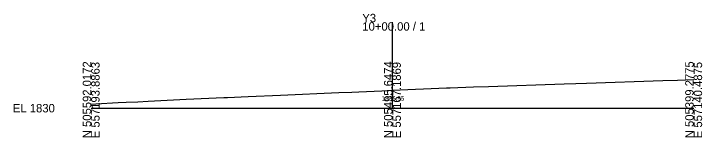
# Model space of a CAD drawing. Extents: x -26 to 1503, y -10 to 2064.
# Drawn here: x -25.7 to 202.8, y -9.7 to 31.5 of the extents above; entities that cross this region are included whole.
import ezdxf

# ---------------------------------------------------------------- set-up
doc = ezdxf.new("R2010")
doc.units = 0
for name, color, linetype in [('Default', 7, 'Continuous'), ('Exist Cross Section Cell', 7, 'Continuous'), ('Exist XS Center Line Elevation Label', 7, 'Continuous'), ('Exist XS Ground Line', 7, 'Continuous')]:
    doc.layers.add(name, color=color, linetype=linetype)

msp = doc.modelspace()

# ---------------------------------------------------------------- linework, layer by layer
at = {"layer": 'Exist Cross Section Cell'}
for p, q in [((100, 0), (100, 28.63)), ((0, 0), (100, 0)), ((100, 0), (200, 0))]:
    msp.add_line(p, q, dxfattribs=at)
at = {"layer": 'Exist XS Ground Line'}
for p, q in [((164.46, 8.31), (189.72, 9.17)), ((189.72, 9.17), (194.62, 9.34)), ((194.62, 9.34), (200, 9.54)), ((119.18, 6.78), (126.95, 7.06)), ((126.95, 7.06), (131.92, 7.21)), ((131.92, 7.21), (156.99, 8.06)), ((156.99, 8.06), (160.86, 8.19)), ((160.86, 8.19), (164.46, 8.31)), ((62.9, 4.35), (82.18, 5.18)), ((82.18, 5.18), (86.51, 5.37)), ((86.51, 5.37), (88.9, 5.47)), ((88.9, 5.47), (96.5, 5.8)), ((96.5, 5.8), (100, 5.95)), ((100, 5.95), (117.91, 6.74)), ((117.91, 6.74), (119.18, 6.78)), ((15.46, 2.15), (18.9, 2.35)), ((18.9, 2.35), (31.48, 3.03)), ((31.48, 3.03), (44.03, 3.53)), ((44.03, 3.53), (45.3, 3.59)), ((45.3, 3.59), (52.11, 3.88)), ((52.11, 3.88), (62.9, 4.35)), ((0, 1.35), (1.52, 1.46)), ((1.52, 1.46), (8.93, 1.88)), ((8.93, 1.88), (11.57, 2.01)), ((11.57, 2.01), (15.46, 2.15))]:
    msp.add_line(p, q, dxfattribs=at)

# ---------------------------------------------------------------- texts
at = {"layer": 'Default'}
msp.add_text('-', height=0.0001, dxfattribs=at).set_placement((0, 0))
at = {"layer": 'Exist Cross Section Cell'}
for s, p in [('Y3', (90, 28.63)), ('10+00.00 / 1', (90, 25.83)), ('EL 1830', (-26, -1.4))]:
    msp.add_text(s, height=2.8, dxfattribs=at).set_placement(p)
for s, p in [('N 505592.0172', (0, -10)), ('E 557193.8863', (2.8, -10)), ('N 505495.6474', (100, -10)), ('E 557167.1869', (102.8, -10)), ('N 505399.2775', (200, -10)), ('E 557140.4875', (202.8, -10))]:
    msp.add_text(s, height=2.8, rotation=90, dxfattribs=at).set_placement(p)
at = {"layer": 'Exist XS Center Line Elevation Label'}
msp.add_text('1835.95', height=1.5, dxfattribs=at).set_placement((96.44, 2.52))

doc.saveas('drawing.dxf')
